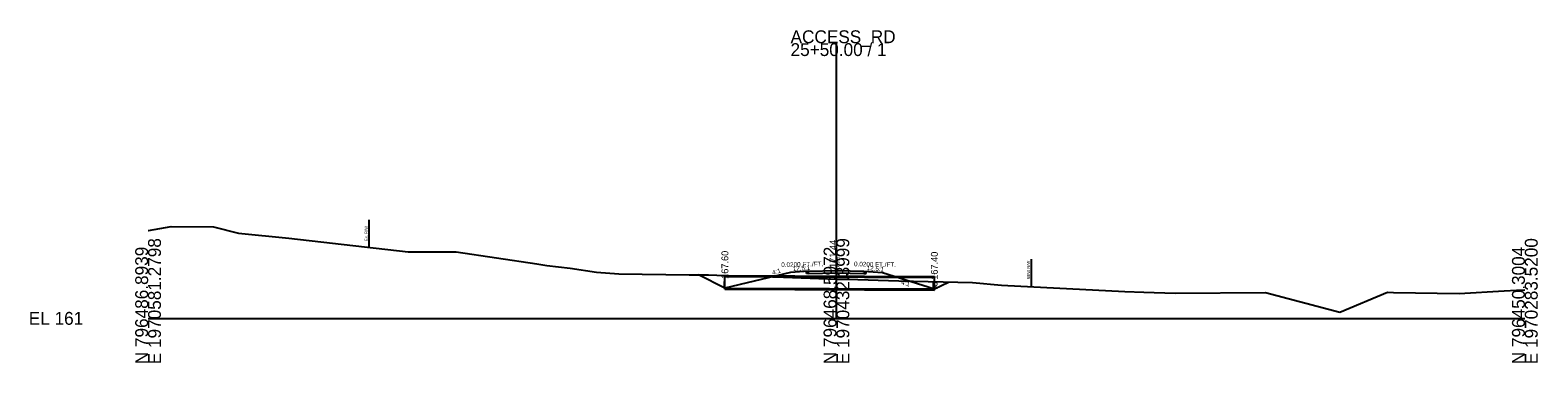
# Model space of a CAD drawing. Extents: x 27306 to 1891059, y 5381 to 776288.
# Drawn here: x 28306 to 28634.5, y 6880.7 to 6953.3 of the extents above; entities that cross this region are included whole.
import ezdxf

# ---------------------------------------------------------------- set-up
doc = ezdxf.new("R2010")
doc.units = 0
for name, color, linetype in [('RD_EX_BldgApp', 7, 'Continuous'), ('RD_EX_H2O_BlueLn', 7, 'Continuous'), ('RD_EX_RailRoad', 7, 'Continuous'), ('RD_HC_Cl', 7, 'Continuous'), ('RD_HC_Data', 7, 'Continuous'), ('RD_HC_Data_Tic', 7, 'Continuous'), ('RD_HC_TX_Sta50', 7, 'Continuous'), ('RD_PD_ALT2_CL', 7, 'Continuous'), ('RD_PD_ALT3_CL', 7, 'Continuous'), ('RD_PD_ALT5_CL', 7, 'Continuous'), ('RD_PD_Final_Cl', 7, 'Continuous'), ('RD_PD_Final_TrvlWay', 7, 'Continuous'), ('RD_PD_MedBWall', 7, 'Continuous'), ('RD_SMD_Misc', 7, 'Continuous'), ('RD_TX_RoadID', 7, 'Continuous')]:
    doc.layers.add(name, color=color, linetype=linetype)

msp = doc.modelspace()

# ---------------------------------------------------------------- linework, layer by layer
at = {"layer": 'RD_EX_H2O_BlueLn'}
for p, q in [((28475.65, 6900.75), (28471.65, 6900.43)), ((28487.65, 6900.75), (28491.65, 6900.43))]:
    msp.add_line(p, q, dxfattribs=at)
at = {"layer": 'RD_EX_RailRoad'}
for p, q in [((28475.15, 6900.49), (28475.65, 6900.5)), ((28475.15, 6900.24), (28475.15, 6900.49)), ((28475.65, 6900.25), (28475.15, 6900.24)), ((28475.65, 6900.5), (28475.65, 6900.75)), ((28475.65, 6900.25), (28481.65, 6900.37)), ((28481.65, 6900.37), (28487.65, 6900.25)), ((28487.65, 6900.5), (28487.65, 6900.75)), ((28488.15, 6900.49), (28487.65, 6900.5)), ((28487.65, 6900.25), (28488.15, 6900.24)), ((28488.15, 6900.24), (28488.15, 6900.49))]:
    msp.add_line(p, q, dxfattribs=at)
at = {"layer": 'RD_HC_Cl'}
for p, q in [((28481.65, 6890.44), (28481.65, 6950.41)), ((28331.65, 6890.44), (28481.65, 6890.44)), ((28481.65, 6890.44), (28631.65, 6890.44))]:
    msp.add_line(p, q, dxfattribs=at)
at = {"layer": 'RD_PD_ALT5_CL'}
for p, q in [((28457.34, 6897.04), (28451.59, 6899.91)), ((28471.65, 6900.43), (28457.34, 6897.04)), ((28491.65, 6900.43), (28502.98, 6896.84)), ((28502.98, 6896.84), (28506.03, 6898.36))]:
    msp.add_line(p, q, dxfattribs=at)
at = {"layer": 'RD_PD_Final_Cl'}
msp.add_lwpolyline([(28331.65, 6909.59), (28331.71, 6909.59), (28336.69, 6910.43), (28345.87, 6910.42), (28351.35, 6908.99), (28362.33, 6907.89), (28388.32, 6904.94), (28398.76, 6904.91), (28416.38, 6902.3), (28418.51, 6901.98), (28423.61, 6901.38), (28429.33, 6900.52), (28434.21, 6900.16), (28449.59, 6899.96), (28452.39, 6899.89), (28453.78, 6899.89), (28455.62, 6899.86), (28470.12, 6899.41), (28481.65, 6899.01), (28482.53, 6898.98), (28484.06, 6898.95), (28495.27, 6898.61), (28511.3, 6898.24), (28517.59, 6897.7), (28544.51, 6896.26), (28548.61, 6896.15), (28555.44, 6895.9), (28575.15, 6896.05), (28591.33, 6891.76), (28601.75, 6896.13), (28603.01, 6896.11), (28617.34, 6895.88), (28627.16, 6896.45), (28629.84, 6896.56), (28631.65, 6896.63)], dxfattribs=at)
at = {"layer": 'RD_PD_Final_TrvlWay'}
msp.add_line((28379.74, 6911.92), (28379.74, 6905.92), dxfattribs=at)
at = {"layer": 'RD_PD_MedBWall'}
for p, q in [((28475.65, 6900.75), (28481.65, 6900.87)), ((28481.65, 6900.87), (28487.65, 6900.75))]:
    msp.add_line(p, q, dxfattribs=at)
at = {"layer": 'RD_SMD_Misc'}
for p, q in [((28457.34, 6896.79), (28457.35, 6899.79)), ((28457.35, 6899.79), (28502.99, 6899.59)), ((28457.35, 6899.54), (28502.99, 6899.34)), ((28502.98, 6896.59), (28502.99, 6899.59)), ((28457.34, 6897.04), (28502.98, 6896.84)), ((28457.34, 6896.79), (28502.98, 6896.59))]:
    msp.add_line(p, q, dxfattribs=at)
at = {"layer": 'RD_TX_RoadID'}
msp.add_line((28524.1, 6903.35), (28524.1, 6897.35), dxfattribs=at)

# ---------------------------------------------------------------- texts
at = {"layer": 'RD_EX_BldgApp'}
msp.add_text('169.57', height=0.8, rotation=90, dxfattribs=at).set_placement((28482.35, 6901.04))
at = {"layer": 'RD_HC_Cl'}
for s, p in [('ACCESS_RD', (28471.65, 6950.41)), ('25+50.00 / 1', (28471.65, 6947.61)), ('EL 161', (28305.65, 6889.04))]:
    msp.add_text(s, height=2.8, dxfattribs=at).set_placement(p)
for s, p in [('N 796486.8939', (28331.65, 6880.44)), ('E 1970581.2798', (28334.45, 6880.44)), ('N 796468.5972', (28481.65, 6880.44)), ('E 1970432.3999', (28484.45, 6880.44)), ('N 796450.3004', (28631.65, 6880.44)), ('E 1970283.5200', (28634.45, 6880.44))]:
    msp.add_text(s, height=2.8, rotation=90, dxfattribs=at).set_placement(p)
at = {"layer": 'RD_HC_Data'}
msp.add_text(' 171.44', height=1.5, rotation=90, dxfattribs=at).set_placement((28481.65, 6900.87))
at = {"layer": 'RD_HC_Data_Tic'}
for rotation, p in [(4.5739, (28472.15, 6900.72)), (355.4261, (28488.19, 6900.96))]:
    msp.add_text('12.5:1', height=1, rotation=rotation, dxfattribs=at).set_placement(p)
at = {"layer": 'RD_HC_TX_Sta50'}
for s, rotation, p in [('0.0200 FT./FT.', 1.1458, (28469.63, 6901.63)), ('0.0200 FT./FT.', 358.8542, (28485.47, 6901.8)), ('4:1', 15.6461, (28467.77, 6899.9)), ('4:1', 344.3539, (28495.68, 6897.87))]:
    msp.add_text(s, height=1, rotation=rotation, dxfattribs=at).set_placement(p)
at = {"layer": 'RD_PD_ALT2_CL'}
for s, p in [('167.60', (28458.09, 6899.04)), ('167.40', (28503.73, 6898.84))]:
    msp.add_text(s, height=1.5, rotation=90, dxfattribs=at).set_placement(p)
at = {"layer": 'RD_PD_ALT3_CL'}
for s, p in [('L', (28456.83, 6897.04)), ('R', (28502.39, 6896.84))]:
    msp.add_text(s, height=1.5, dxfattribs=at).set_placement(p)
at = {"layer": 'RD_PD_Final_TrvlWay'}
msp.add_text('Ex. R/W ', height=0.65, rotation=90, dxfattribs=at).set_placement((28379.49, 6907.3))
at = {"layer": 'RD_TX_RoadID'}
msp.add_text('NEW R/W ', height=0.65, rotation=90, dxfattribs=at).set_placement((28523.83, 6898.91))

doc.saveas('drawing.dxf')
